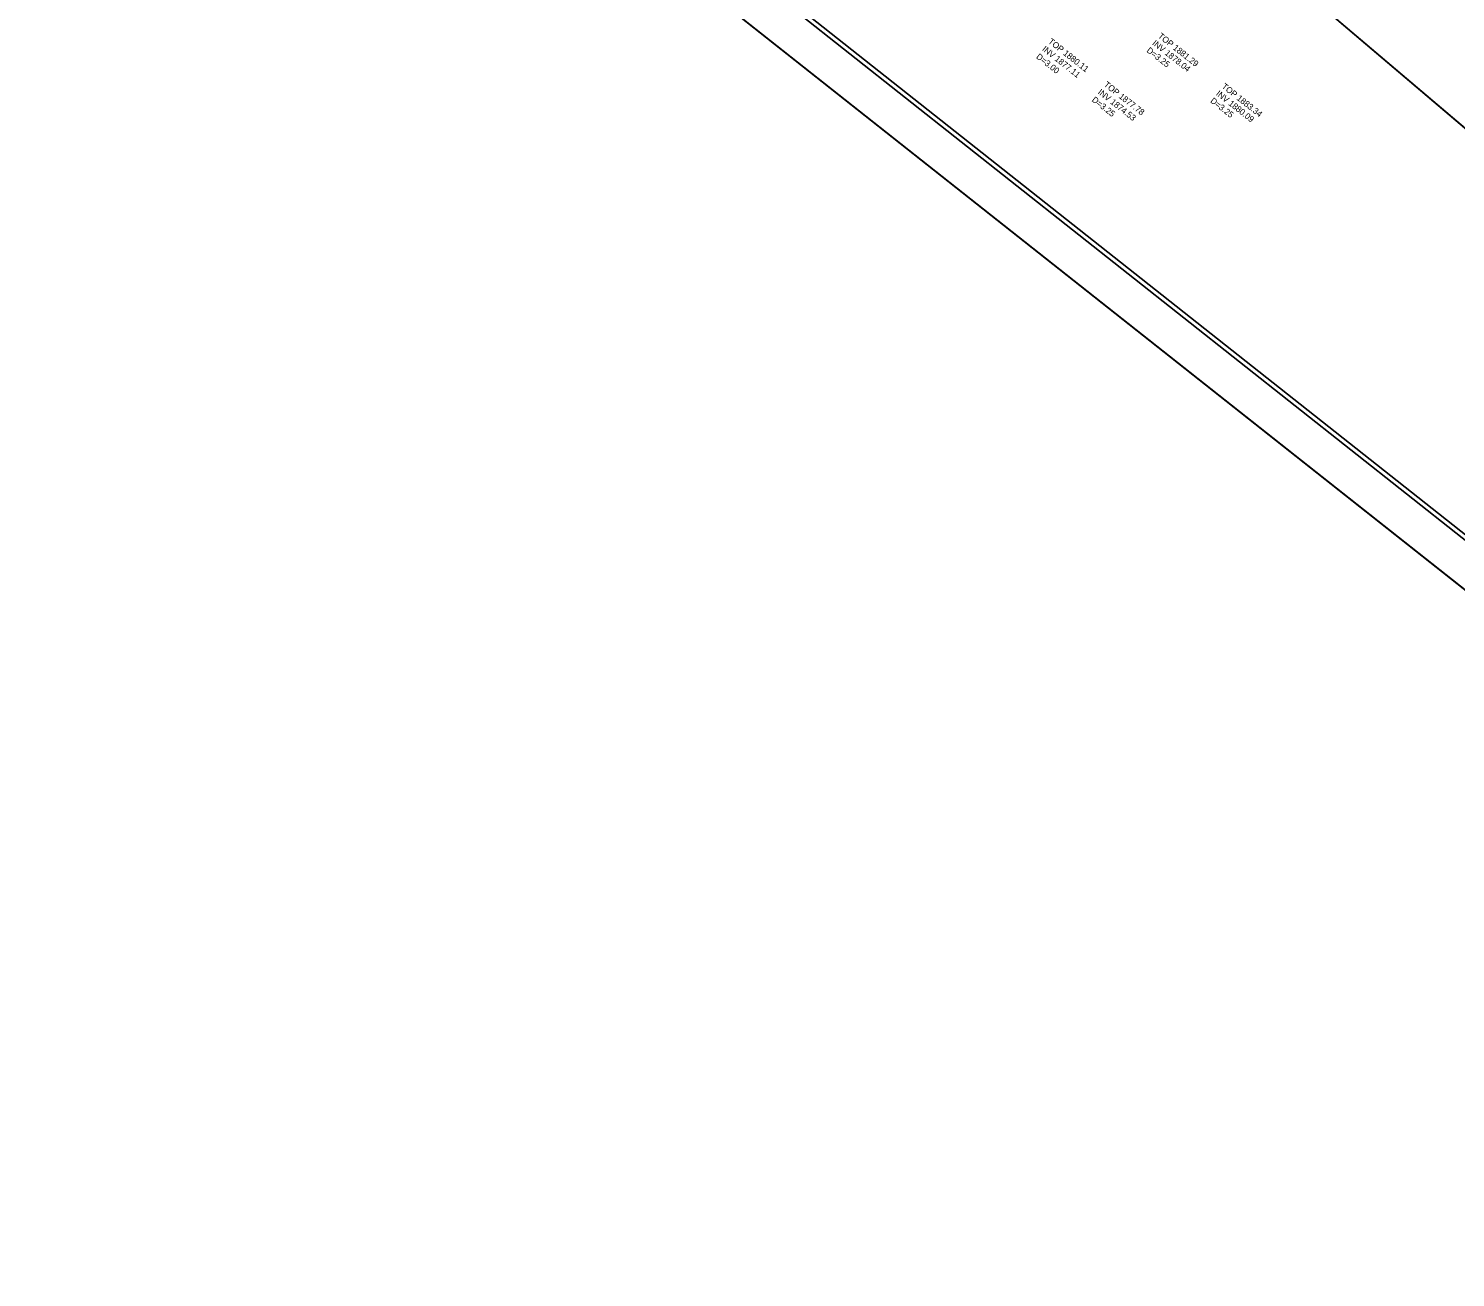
# Model space of a CAD drawing. Extents: x 557005 to 559009, y 505746 to 507841.
# Drawn here: x 557005 to 557823, y 505933 to 506649 of the extents above; entities that cross this region are included whole.
import ezdxf

# ---------------------------------------------------------------- set-up
doc = ezdxf.new("R2010")
doc.units = 0
for name, color, linetype in [('DTM Contours Minor Text', 7, 'Continuous'), ('Matchline', 7, 'Continuous'), ('Scratch_Level_5', 7, 'Continuous'), ('Sheet Border Standard 30in CELL', 7, 'Continuous'), ('Sheet Cutting Line CELL', 7, 'Continuous'), ('Sheet Plot Border Inside CELL', 7, 'Continuous'), ('Sheet Plot Border Outside CELL', 7, 'Continuous')]:
    doc.layers.add(name, color=color, linetype=linetype)

msp = doc.modelspace()

# ---------------------------------------------------------------- linework, layer by layer
at = {"layer": 'Matchline'}
msp.add_line((557889.73, 506539.36), (557425.46, 506933.59), dxfattribs=at)
at = {"layer": 'Scratch_Level_5'}
msp.add_lwpolyline([(558502.21, 506199.86), (558069.07, 506542.35), (558000.13, 506451.2), (557930.66, 506511.32), (557889.73, 506539.36), (557425.46, 506933.59), (557393.31, 506960), (557371.36, 506969.71), (557385.34, 506999.14), (557443.19, 507138.35), (557378.87, 507175.51), (557803.85, 507716.87), (558807.23, 506891.56), (558715.12, 506775.08), (558872.03, 506651.01)], close=True, dxfattribs=at)
at = {"layer": 'Sheet Border Standard 30in CELL'}
msp.add_lwpolyline([(558979.69, 506787.13), (557803.06, 507717.49), (557151.81, 506893.85), (558328.44, 505963.5)], close=True, dxfattribs=at)
at = {"layer": 'Sheet Cutting Line CELL'}
msp.add_line((557005.31, 506977.82), (558326.27, 505933.34), dxfattribs=at)
at = {"layer": 'Sheet Plot Border Inside CELL'}
msp.add_lwpolyline([(558991.07, 506781.38), (557683.84, 507815), (557029.43, 506987.37), (558336.66, 505953.74)], close=True, dxfattribs=at)
at = {"layer": 'Sheet Plot Border Outside CELL'}
msp.add_lwpolyline([(559008.53, 506796.2), (557687.57, 507840.68), (557005.31, 506977.82), (558326.27, 505933.34)], close=True, dxfattribs=at)

# ---------------------------------------------------------------- texts
at = {"layer": 'DTM Contours Minor Text'}
for s, p in [('TOP 1880.11', (557589.05, 506640.82)), ('INV 1878.04', (557648.67, 506639.81)), ('TOP 1881.29', (557651.92, 506643.92)), ('D=3.00', (557582.15, 506632.1)), ('INV 1877.11', (557585.6, 506636.46)), ('D=3.25', (557645.41, 506635.69)), ('TOP 1877.78', (557620.92, 506616.12)), ('TOP 1883.34', (557688.43, 506615.06)), ('D=3.25', (557614.03, 506607.4)), ('INV 1874.53', (557617.48, 506611.76)), ('D=3.25', (557681.91, 506606.82)), ('INV 1880.09', (557685.17, 506610.94))]:
    msp.add_text(s, height=3.5, rotation=321.66667, dxfattribs=at).set_placement(p)

doc.saveas('drawing.dxf')
